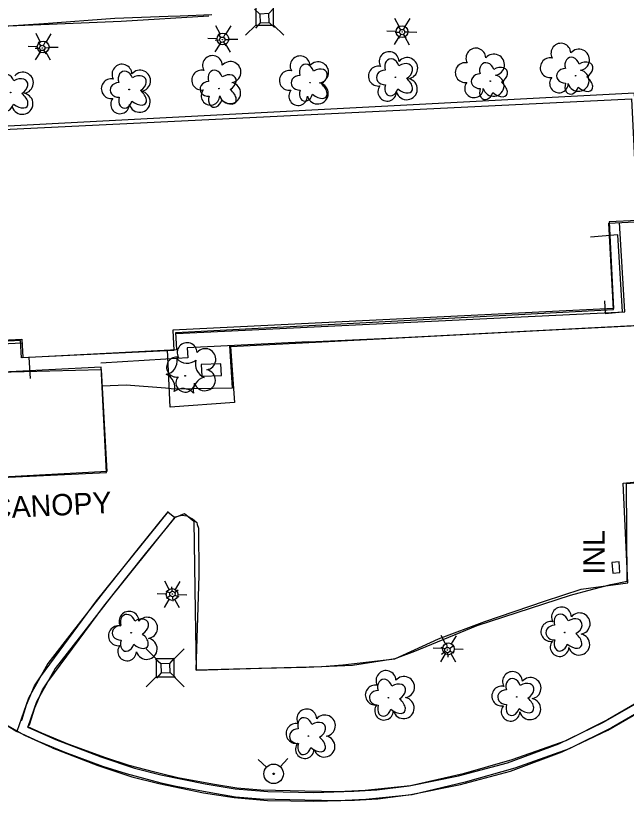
# Model space of a CAD drawing. Extents: x 588843 to 2552415, y 180129 to 269402.
# Drawn here: x 594930 to 595101, y 184366.5 to 184586.7 of the extents above; entities that cross this region are included whole.
import ezdxf

# ---------------------------------------------------------------- set-up
doc = ezdxf.new("R2010")
doc.units = 0
for name, color, linetype in [('E_BLD', 7, 'Continuous'), ('E_BLD_HvyDash', 7, 'Continuous'), ('E_BLD_Text', 7, 'Continuous'), ('E_DWY', 7, 'Continuous'), ('E_LAND_Vegetation', 7, 'Continuous'), ('E_LTG', 7, 'Continuous'), ('E_PATH_Sidewalk', 7, 'Continuous'), ('E_RDWY_C_and_G', 7, 'Continuous'), ('E_UTL_AG_Bold', 7, 'Continuous'), ('E_UTL_WHydrant', 7, 'Continuous'), ('Level 11', 7, 'Continuous'), ('Level 12', 7, 'Continuous'), ('Level 14', 7, 'Continuous'), ('Level 15', 7, 'Continuous'), ('Level 17', 7, 'Continuous'), ('Level 18', 7, 'Continuous'), ('Level 21', 7, 'Continuous')]:
    doc.layers.add(name, color=color, linetype=linetype)

# ---------------------------------------------------------------- blocks, each defined once
blk = doc.blocks.new('LPOL_4')
at = {"layer": 'E_LTG'}
for p, q in [((-13.1, 0), (-4.9, 0)), ((-2.5, 4.3), (-6.6, 11.4)), ((2.5, 4.3), (6.6, 11.4)), ((4.9, 0), (13.1, 0)), ((-6.6, -11.4), (-2.5, -4.3)), ((6.6, -11.4), (2.5, -4.3))]:
    blk.add_line(p, q, dxfattribs=at)
for radius in [4.92, 4.92, 4.92, 0.41]:
    blk.add_circle((0, 0), radius, dxfattribs=at)
blk = doc.blocks.new('PED_3')
at = {"layer": 'E_UTL_AG_Bold'}
for p, q in [((-8.2, 8.2), (-17.5, 17.5)), ((8.2, 8.2), (17.5, 17.5)), ((-8.2, -8.2), (-17.5, -17.5)), ((8.2, -8.2), (17.5, -17.5))]:
    blk.add_line(p, q, dxfattribs=at)
blk.add_lwpolyline([(-8.2, -8.2), (8.2, -8.2), (8.2, 8.2), (-8.2, 8.2)], close=True, dxfattribs=at)
blk = doc.blocks.new('DTRE_4')
at = {"layer": 'E_LAND_Vegetation'}
blk.add_circle((-0.6, 0), 0.601, dxfattribs=at)
for centre, major_axis, ratio in [((-6.1, 17.5), (4.5, -16.3), 0.782863), ((13.3, 9), (-17.3, -9.6), 0.691916), ((-19.3, 0.5), (16.2, -0.4), 0.832022), ((-8.2, -17.2), (5.9, 15.9), 0.716896), ((11.6, -12.2), (-16.4, 15), 0.560249)]:
    blk.add_ellipse(centre, major_axis=major_axis, ratio=ratio, start_param=1.570796, end_param=4.712389, dxfattribs=at)
blk = doc.blocks.new('HYD_3')
at = {"layer": 'E_UTL_WHydrant'}
for p, q in [((-12.6, 12.6), (-27.3, 27.3)), ((12.6, 12.6), (27.3, 27.3))]:
    blk.add_line(p, q, dxfattribs=at)
for radius in [18, 1.38]:
    blk.add_circle((0, 0), radius, dxfattribs=at)
blk = doc.blocks.new('CTRE_4')
at = {"layer": 'E_LAND_Vegetation'}
blk.add_circle((0, 0), 0.733, dxfattribs=at)
for centre, start, end in [((-39.3, 29.4), 280.2067, 5.9716), ((5.9, 49), 220.2113, 305.9762), ((45.4, 19.3), 160.2113, 245.9762), ((-45.4, -19.3), 340.2113, 65.9762), ((39.5, -29.6), 100.2511, 185.9272), ((-5.9, -49), 40.2113, 125.9762)]:
    blk.add_arc(centre, 25.8, start, end, dxfattribs=at)
blk = doc.blocks.new('CANOPY_1')
at = {"layer": 'E_BLD_Text'}
blk.add_text('CANOPY', height=39.37, dxfattribs=at).set_placement((-106.7, -19.7))

msp = doc.modelspace()

# ---------------------------------------------------------------- linework, layer by layer
at = {"layer": 'E_BLD'}
msp.add_lwpolyline([(594931.34, 184495.6), (594915.76, 184494.83), (594915.75, 184495.15), (594887.49, 184493.76), (594884.59, 184552.69), (594913.65, 184554.12), (594912.97, 184554.09), (594984.08, 184557.57), (595102.54, 184563.39), (595104.21, 184529.31), (595096.26, 184528.92), (595097.45, 184504.62), (594974.02, 184498.56), (594974.3, 184492.84), (594931.58, 184490.74)], close=True, dxfattribs=at)
at = {"layer": 'E_BLD_HvyDash'}
for points in [[(594955.54, 184458.88), (594926.41, 184457.28), (594925.02, 184486.76), (594953.9, 184487.5)], [(594953.9, 184487.5), (594955.54, 184458.88)]]:
    msp.add_lwpolyline(points, dxfattribs=at)
at = {"layer": 'E_DWY'}
for points in [[(594853.87, 184578.66), (594856.32, 184579.18), (594875.82, 184580.94), (594916.75, 184583.36), (594959.55, 184585.14), (594984.11, 184586.69)], [(595171.81, 184472.65), (595167.63, 184473.03), (595154.87, 184476.19), (595146.63, 184479.73), (595142.36, 184483.18), (595140.93, 184485.01), (595139.64, 184487.73), (595138.95, 184488.95), (595138.65, 184498.88), (595121.13, 184497.84), (595120.87, 184500.58), (595076.53, 184498.31), (595017.63, 184495.3), (594990.15, 184493.86), (594991.23, 184478.27), (594973.21, 184476.95), (594972.49, 184493.05)], [(594934.07, 184485.02), (594933.77, 184490.85)], [(594974.75, 184446.16), (594976.54, 184446.68), (594977.93, 184446.5), (594979.53, 184445.64), (594980.68, 184444.6), (594980.83, 184444.05), (594981.16, 184443.03), (594981.25, 184429.77), (594980.42, 184403.34), (595015.75, 184404.22), (595021.63, 184404.73), (595036.16, 184406.41), (595048.39, 184412.02), (595061.45, 184416.88), (595078.12, 184422.57), (595088.4, 184425.96), (595101.51, 184427.72), (595100.2, 184455.68), (595119.69, 184457.51)], [(594931.59, 184389.19), (594931.65, 184389.24), (594933.03, 184393.52), (594935.28, 184398.87), (594936.9, 184401.38), (594952.64, 184422.65), (594972.81, 184447.72)], [(594933.3, 184387.36), (594933.83, 184387.85), (594935.37, 184392.65), (594937.5, 184397.7), (594938.96, 184399.96), (594954.62, 184421.12), (594974.75, 184446.16)]]:
    msp.add_lwpolyline(points, dxfattribs=at)
at = {"layer": 'E_PATH_Sidewalk'}
msp.add_lwpolyline([(595094.93, 184506.72), (595095.17, 184503.17), (595100.02, 184503.66), (595098.68, 184525.26), (595091.02, 184524.64)], dxfattribs=at)
at = {"layer": 'E_RDWY_C_and_G'}
for points in [[(594840.99, 184416.47), (594853.52, 184416.52), (594859.86, 184416.05), (594867.1, 184415.1), (594873.59, 184413.68), (594882.4, 184411.05), (594888.77, 184408.67), (594896.76, 184405.03), (594901.36, 184402.7), (594932.46, 184384.96), (594940.08, 184381.5)], [(594941.11, 184383.77), (594953.78, 184378.89), (594963.26, 184375.72), (594970.64, 184373.86), (594983.05, 184371.31), (594991.5, 184369.98), (595000.61, 184369.17), (595013.47, 184368.96), (595024.75, 184369.29), (595031.2, 184369.64), (595040.25, 184370.8), (595054.06, 184373.61), (595067.8, 184377.25), (595082.11, 184382.58), (595094.67, 184388.61), (595108.85, 184396.75)], [(594940.21, 184381.44), (594952.94, 184376.53), (594962.55, 184373.32), (594970.08, 184371.43), (594982.6, 184368.85), (594991.19, 184367.49), (595000.48, 184366.67), (595013.49, 184366.46), (595024.85, 184366.79), (595031.43, 184367.15), (595040.66, 184368.33), (595054.63, 184371.17), (595068.56, 184374.86), (595083.09, 184380.28), (595095.84, 184386.39), (595110.09, 184394.58)], [(594933.3, 184387.36), (594933.6, 184387.18), (594941.11, 184383.77)]]:
    msp.add_lwpolyline(points, dxfattribs=at)
at = {"layer": 'Level 11'}
for points in [[(595163.36, 184448.74), (595157.09, 184440.22), (595149.33, 184431.32), (595142.04, 184423.12), (595133.82, 184415.06), (595127.52, 184409.82), (595118.72, 184402.98), (595108.04, 184396.38), (595095.75, 184389.27), (595084.08, 184383.45), (595069.02, 184378.08), (595055.31, 184374.2), (595040.62, 184370.76), (595027.88, 184369.5), (595020.28, 184369.11), (595011.01, 184369.29)], [(595165.37, 184447.26), (595159.04, 184438.66), (595151.2, 184429.67), (595143.85, 184421.39), (595135.49, 184413.21), (595129.09, 184407.87), (595120.15, 184400.92), (595109.32, 184394.23), (595096.93, 184387.07), (595085.06, 184381.14), (595069.78, 184375.7), (595055.94, 184371.78), (595041.03, 184368.29), (595028.06, 184367), (595020.32, 184366.61), (595010.96, 184366.79)], [(594907.81, 184399.6), (594915.61, 184395.1), (594930.27, 184386.02)], [(594971.15, 184374.06), (594968.95, 184374.6), (594961.73, 184376.51), (594955.19, 184378.6), (594944.7, 184382.47), (594937.33, 184385.53), (594933.37, 184387.34)], [(594971.13, 184371.49), (594968.33, 184372.18), (594961.03, 184374.11), (594954.38, 184376.23), (594943.79, 184380.14), (594936.33, 184383.24), (594930.27, 184386.02)], [(595011.01, 184369.29), (594998.63, 184369.55), (594991.91, 184370.13), (594985.1, 184371.25), (594975.44, 184373), (594971.15, 184374.06)], [(595010.96, 184366.79), (594998.49, 184367.05), (594991.59, 184367.65), (594984.67, 184368.79), (594974.91, 184370.56), (594971.13, 184371.49)]]:
    msp.add_lwpolyline(points, dxfattribs=at)
at = {"layer": 'Level 12'}
for points in [[(595103.37, 184564.96), (594885.16, 184553.5)], [(594888.17, 184493.75), (594931.68, 184496.04), (594931.95, 184490.86), (594975.12, 184493.12), (594974.87, 184497.91), (595097.42, 184504.34), (595096.15, 184528.53), (595105.26, 184529.01), (595103.37, 184564.96)], [(594955.37, 184458.65), (594953.91, 184488.17), (594924.5, 184486.71), (594925.96, 184457.2), (594955.37, 184458.65)]]:
    msp.add_lwpolyline(points, dxfattribs=at)
at = {"layer": 'Level 14'}
for p, q in [((595037.41, 184583.64), (595036.21, 184585.94)), ((595039.11, 184583.63), (595040.48, 184585.86)), ((594987.24, 184581.59), (594986.04, 184583.89)), ((594988.94, 184581.58), (594990.3, 184583.81)), ((594936.87, 184579.36), (594935.67, 184581.67)), ((594938.57, 184579.36), (594939.93, 184581.59)), ((595036.58, 184582.27), (595033.97, 184582.35)), ((595039.85, 184582.18), (595042.37, 184582.12)), ((594986.4, 184580.23), (594983.8, 184580.3)), ((594987.16, 184578.73), (594985.79, 184576.54)), ((594988.79, 184578.69), (594990.04, 184576.51)), ((594989.67, 184580.13), (594992.19, 184580.07)), ((595037.33, 184580.78), (595035.97, 184578.59)), ((595038.97, 184580.74), (595040.21, 184578.56)), ((594936.03, 184578), (594933.43, 184578.07)), ((594936.79, 184576.51), (594935.43, 184574.32)), ((594938.43, 184576.46), (594939.67, 184574.29)), ((594939.31, 184577.91), (594941.83, 184577.84)), ((594973, 184425.86), (594971.8, 184428.16)), ((594974.7, 184425.85), (594976.06, 184428.08)), ((594972.16, 184424.5), (594969.56, 184424.57)), ((594972.92, 184423.01), (594971.55, 184420.82)), ((594974.55, 184422.96), (594975.8, 184420.78)), ((594975.43, 184424.4), (594977.95, 184424.34)), ((595050.42, 184410.63), (595049.22, 184412.93)), ((595052.12, 184410.62), (595053.48, 184412.85)), ((595049.58, 184409.27), (595046.98, 184409.34)), ((595052.85, 184409.18), (595055.37, 184409.11)), ((595050.34, 184407.77), (595048.97, 184405.58)), ((595051.97, 184407.73), (595053.22, 184405.55))]:
    msp.add_line(p, q, dxfattribs=at)
for centre in [(595038.21, 184582.21), (594988.03, 184580.16), (594937.67, 184577.93), (594973.79, 184424.43), (595051.21, 184409.2)]:
    msp.add_circle(centre, 1.64, dxfattribs=at)
at = {"layer": 'Level 15'}
msp.add_lwpolyline([(595097.24, 184430.45), (595099.23, 184430.58), (595099.03, 184433.57), (595097.04, 184433.44), (595097.24, 184430.45)], dxfattribs=at)
at = {"layer": 'Level 17'}
for points in [[(594972.73, 184586.48), (594957.77, 184585.95), (594937.84, 184584.4), (594923.51, 184583.44), (594922.71, 184583.38)], [(594984.94, 184586.91), (594976.02, 184586.59), (594972.73, 184586.48)], [(594974.89, 184497.57), (595100.64, 184503.68), (595099.19, 184528.69)], [(594885.58, 184527.53), (594883.83, 184527.44), (594884.51, 184512.32), (594885.46, 184492.65), (594889.8, 184492.8), (594900.27, 184493.38), (594916.56, 184494.2), (594931.73, 184494.99)], [(595012.05, 184495.29), (595036.6, 184496.41), (595072.38, 184498.27), (595104.83, 184499.95), (595120.33, 184500.56)], [(595012.05, 184495.29), (594978.05, 184493.55), (594978.22, 184490.73), (594972.02, 184490.36)], [(594971.95, 184482.33), (594974.41, 184482.12), (594990.75, 184482.39), (594989.93, 184494.16)], [(594972.02, 184490.36), (594953.86, 184489.3)], [(594954.17, 184482.9), (594960.93, 184483.25), (594971.95, 184482.33)], [(595011.37, 184404.06), (595024.33, 184404.64), (595036.32, 184406.45), (595041.77, 184408.54), (595059.27, 184415.7), (595085.4, 184424.21), (595091.69, 184425.93), (595096.76, 184427.27), (595101.28, 184428.15), (595101.08, 184455.57), (595125.34, 184457.55), (595131.15, 184457.75), (595134.71, 184457.86), (595138.62, 184457.22), (595146.3, 184455.29), (595160.03, 184451.56), (595162.59, 184449.88), (595163.36, 184448.74)], [(594972.63, 184447.62), (594971.69, 184446.47)], [(594972.63, 184447.62), (594974.56, 184446.03)], [(594974.56, 184446.03), (594977.23, 184447.11), (594979.89, 184444.98), (594980.27, 184419.83), (594980.58, 184403.18), (594998.87, 184403.78), (595011.37, 184404.06)], [(594971.69, 184446.47), (594964.25, 184437.37), (594955.52, 184426.32), (594945.76, 184413.85), (594938.93, 184405.04), (594933.52, 184395.39), (594930.27, 184386.02)], [(594974.56, 184446.03), (594971.66, 184442.48)], [(594971.66, 184442.48), (594966.2, 184435.8), (594957.48, 184424.78), (594947.73, 184412.32), (594941.02, 184403.65), (594935.81, 184394.36), (594933.37, 184387.34)]]:
    msp.add_lwpolyline(points, dxfattribs=at)
at = {"layer": 'Level 18'}
for centre, radius, start, end in [((595082.72, 184576.18), 2.78, 1.3946, 209.1675), ((595034.59, 184573.82), 2.78, 1.3946, 209.1675), ((595058.91, 184574.81), 2.78, 1.3946, 209.1675), ((595087.76, 184574.32), 2.97, 278.4237, 139.6575), ((594985.08, 184572.72), 2.78, 1.3946, 209.1675), ((595009.64, 184572.63), 2.78, 1.3946, 209.1675), ((595039.64, 184571.97), 2.97, 278.4237, 139.6575), ((595063.95, 184572.95), 2.97, 278.4237, 139.6575), ((595079.72, 184572.1), 2.78, 78.0716, 279.0826), ((594959.74, 184570.3), 2.78, 1.3946, 209.1675), ((594990.12, 184570.86), 2.97, 278.4237, 139.6575), ((595014.68, 184570.77), 2.97, 278.4237, 139.6575), ((595031.59, 184569.75), 2.78, 78.0716, 279.0826), ((595055.91, 184570.73), 2.78, 78.0716, 279.0826), ((594931.95, 184567.88), 2.97, 278.4237, 139.6575), ((594964.78, 184568.44), 2.97, 278.4237, 139.6575), ((594982.08, 184568.64), 2.78, 78.0716, 279.0826), ((595006.64, 184568.55), 2.78, 78.0716, 279.0826), ((595063.84, 184567.09), 2.97, 196.0745, 79.0477), ((595087.65, 184568.47), 2.97, 196.0745, 79.0477), ((594956.74, 184566.22), 2.78, 78.0716, 279.0826), ((594990.01, 184565.01), 2.97, 196.0745, 79.0477), ((595014.57, 184564.91), 2.97, 196.0745, 79.0477), ((595039.53, 184566.11), 2.97, 196.0745, 79.0477), ((595058.37, 184566.33), 2.61, 140.7797, 358.7123), ((595082.18, 184567.7), 2.61, 140.7797, 358.7123), ((594964.67, 184562.59), 2.97, 196.0745, 79.0477), ((594984.54, 184564.24), 2.61, 140.7797, 358.7123), ((595009.1, 184564.15), 2.61, 140.7797, 358.7123), ((595034.06, 184565.35), 2.61, 140.7797, 358.7123), ((594931.84, 184562.02), 2.97, 196.0745, 79.0477), ((594959.2, 184561.83), 2.61, 140.7797, 358.7123), ((594978.01, 184492.24), 2.78, 1.3946, 209.1675), ((594983.06, 184490.38), 2.97, 278.4237, 139.6575), ((594975.01, 184488.16), 2.78, 78.0716, 279.0826), ((594982.94, 184484.52), 2.97, 196.0745, 79.0477), ((594977.47, 184483.76), 2.61, 140.7797, 358.7123), ((595082.9, 184418.14), 2.78, 1.3946, 209.1675), ((594961.71, 184416.93), 2.78, 1.3946, 209.1675), ((594966.76, 184415.07), 2.97, 278.4237, 139.6575), ((595087.94, 184416.28), 2.97, 278.4237, 139.6575), ((595079.9, 184414.06), 2.78, 78.0716, 279.0826), ((594958.71, 184412.85), 2.78, 78.0716, 279.0826), ((594966.65, 184409.21), 2.97, 196.0745, 79.0477), ((595082.36, 184409.66), 2.61, 140.7797, 358.7123), ((595087.83, 184410.43), 2.97, 196.0745, 79.0477), ((594961.18, 184408.45), 2.61, 140.7797, 358.7123), ((595033.71, 184400.32), 2.78, 1.3946, 209.1675), ((595069.16, 184400.03), 2.78, 1.3946, 209.1675), ((595038.75, 184398.47), 2.97, 278.4237, 139.6575), ((595074.2, 184398.17), 2.97, 278.4237, 139.6575), ((595030.71, 184396.25), 2.78, 78.0716, 279.0826), ((595066.16, 184395.95), 2.78, 78.0716, 279.0826), ((595038.64, 184392.61), 2.97, 196.0745, 79.0477), ((595074.09, 184392.32), 2.97, 196.0745, 79.0477), ((595011.52, 184389.53), 2.78, 1.3946, 209.1675), ((595033.17, 184391.85), 2.61, 140.7797, 358.7123), ((595068.62, 184391.55), 2.61, 140.7797, 358.7123), ((595016.56, 184387.67), 2.97, 278.4237, 139.6575), ((595008.52, 184385.46), 2.78, 78.0716, 279.0826), ((595010.98, 184381.06), 2.61, 140.7797, 358.7123), ((595016.45, 184381.82), 2.97, 196.0745, 79.0477)]:
    msp.add_arc(centre, radius, start, end, dxfattribs=at)
at = {"layer": 'Level 21'}
for p, q in [((594997.22, 184584.05), (594994.39, 184581.23)), ((595002.22, 184584.05), (595005.05, 184581.23)), ((594969.33, 184406.36), (594966.5, 184409.19)), ((594974.33, 184406.36), (594977.16, 184409.19)), ((594969.33, 184401.36), (594966.5, 184398.53)), ((594974.33, 184401.36), (594977.16, 184398.53))]:
    msp.add_line(p, q, dxfattribs=at)
for points in [[(594997.22, 184584.05), (595002.22, 184584.05), (595002.22, 184589.05), (594997.22, 184589.05)], [(594969.33, 184401.36), (594974.33, 184401.36), (594974.33, 184406.36), (594969.33, 184406.36)]]:
    msp.add_lwpolyline(points, close=True, dxfattribs=at)
msp.add_lwpolyline([(594982.09, 184485.61), (594987.6, 184485.87), (594987.45, 184489.14), (594981.94, 184488.88), (594982.09, 184485.61)], dxfattribs=at)

# ---------------------------------------------------------------- block references
at = {"layer": 'E_BLD_Text', "xscale": 0.15240030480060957, "yscale": 0.1524003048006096, "rotation": 2.834815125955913}
msp.add_blockref('CANOPY_1', (594939.23, 184449.43), dxfattribs=at)
at = {"layer": 'E_LAND_Vegetation', "yscale": 0.15240030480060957}
for name, p, xscale, rotation in [('DTRE_4', (595036.45, 184569.43), 0.1524003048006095, 2.3276622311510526), ('DTRE_4', (595086.94, 184569.88), 0.1524003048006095, 2.3276622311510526), ('DTRE_4', (594987.02, 184566.26), 0.15240030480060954, 3.4338469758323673), ('DTRE_4', (595012.54, 184567.92), 0.1524003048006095, 2.3276622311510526), ('DTRE_4', (595063.03, 184568.36), 0.1524003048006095, 2.3276622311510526), ('DTRE_4', (594928.65, 184565.15), 0.15240030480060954, 3.4338469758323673), ('DTRE_4', (594961.86, 184565.99), 0.15240030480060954, 3.4338469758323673), ('CTRE_4', (594977.44, 184485.72), 0.1524003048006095, 2.3276622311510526), ('DTRE_4', (594962.42, 184413.71), 0.1524003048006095, 2.3276622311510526), ('DTRE_4', (595083.9, 184413.78), 0.1524003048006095, 2.3276622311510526), ('DTRE_4', (595034.47, 184395.5), 0.1524003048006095, 2.3276622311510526), ('DTRE_4', (595070.43, 184395.7), 0.1524003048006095, 2.3276622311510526), ('DTRE_4', (595012.07, 184384.74), 0.1524003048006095, 2.3276622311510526)]:
    msp.add_blockref(name, p, dxfattribs=dict(at, xscale=xscale, rotation=rotation))
at = {"layer": 'E_LTG'}
for p, xscale, yscale, rotation in [((595038.25, 184582.11), 0.1524003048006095, 0.15240030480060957, 2.3276622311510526), ((594987.85, 184579.95), 0.1524003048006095, 0.15240030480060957, 2.3276622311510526), ((594937.4, 184577.65), 0.1524003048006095, 0.15240030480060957, 2.3276622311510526), ((594973.89, 184424.57), 0.1524003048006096, 0.1524003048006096, -24.21972835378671), ((595050.94, 184408.86), 0.1524003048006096, 0.1524003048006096, -24.21972835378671)]:
    msp.add_blockref('LPOL_4', p, dxfattribs=dict(at, xscale=xscale, yscale=yscale, rotation=rotation))
at = {"layer": 'E_UTL_AG_Bold', "xscale": 0.1524003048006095, "yscale": 0.15240030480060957, "rotation": 2.3276622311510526}
for p in [(594999.69, 184585.97), (594971.95, 184403.76)]:
    msp.add_blockref('PED_3', p, dxfattribs=at)
at = {"layer": 'E_UTL_WHydrant', "xscale": 0.1524003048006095, "yscale": 0.15240030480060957, "rotation": 2.3276622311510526}
msp.add_blockref('HYD_3', (595002.24, 184374.16), dxfattribs=at)

# ---------------------------------------------------------------- texts
at = {"layer": 'Level 15'}
msp.add_text('INL', height=6, rotation=90, dxfattribs=at).set_placement((595094.99, 184430))

doc.saveas('drawing.dxf')
